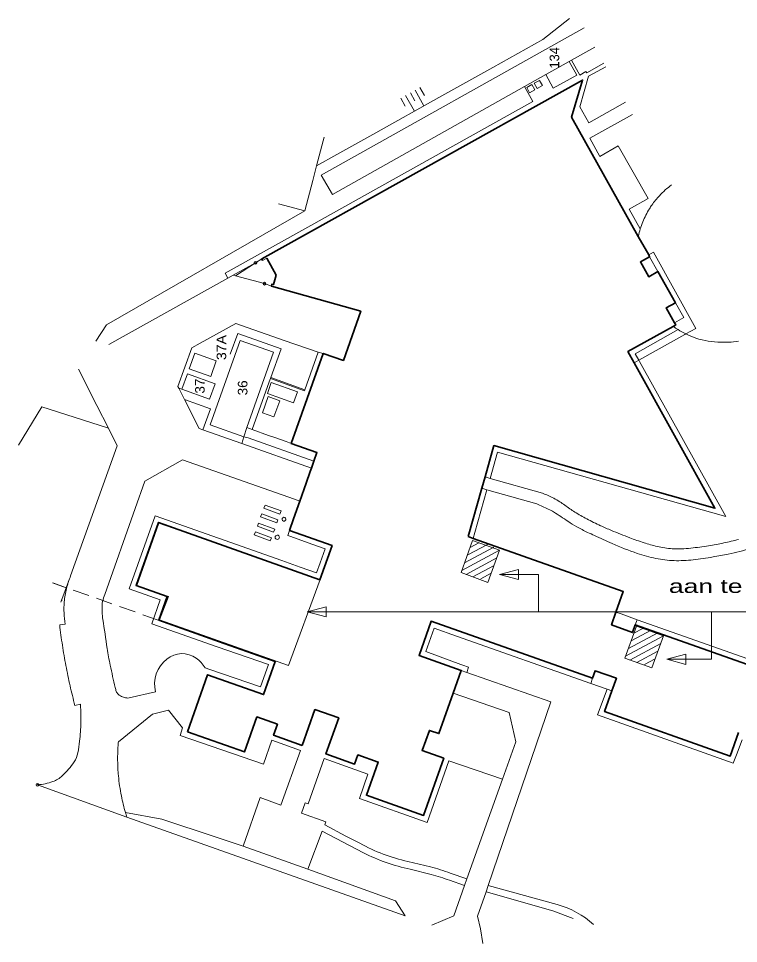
# Model space of a CAD drawing. Extents: x 295824 to 414724, y 24924 to 109024.
# Drawn here: x 390118 to 403291, y 57517 to 74434 of the extents above; entities that cross this region are included whole.
import ezdxf

# ---------------------------------------------------------------- set-up
doc = ezdxf.new("R2010")
doc.units = 0
doc.header["$LTSCALE"] = 100
doc.header["$PDMODE"] = 32
doc.header["$PDSIZE"] = 50
doc.linetypes.add('MEDIUM_DASHED', pattern=[4.5, 3, -1.5])
for name, color, linetype, lineweight in [('16', 7, 'Continuous', 13), ('19', 7, 'Continuous', 13), ('20', 7, 'Continuous', 13), ('22', 7, 'Continuous', 13), ('24', 7, 'Continuous', 13), ('25', 7, 'Continuous', 13), ('26', 7, 'Continuous', 13), ('32', 7, 'Continuous', 13), ('4', 7, 'Continuous', 35), ('40', 7, 'Continuous', 13), ('51', 7, 'Continuous', 13), ('52', 7, 'Continuous', 13), ('58', 7, 'Continuous', 35), ('62', 7, 'Continuous', 13)]:
    doc.layers.add(name, color=color, linetype=linetype, lineweight=lineweight)
doc.layers.add('57', color=7, linetype='Continuous')

msp = doc.modelspace()

# ---------------------------------------------------------------- linework, layer by layer
at = {"layer": '16'}
for p, q in [((398339.7, 64625.4), (398697.8, 64817)), ((398380.9, 64760.9), (398542, 64847.1)), ((398228.2, 64338.8), (398920.2, 64709.2)), ((398279.1, 64479.5), (398814.6, 64766.1)), ((398306.8, 64267.5), (398869.3, 64568.6)), ((398433.3, 64221.8), (398818.4, 64427.9)), ((398575.6, 64184.5), (398767.5, 64287.2)), ((398915.6, 64265.6), (399633.3, 64265.6)), ((399633.3, 63582.1), (399633.3, 64265.6)), ((401379, 63194.2), (401540.1, 63280.5)), ((401226.3, 62772.2), (401918.3, 63142.6)), ((401277.2, 62912.9), (401812.7, 63199.5)), ((401337.8, 63058.7), (401695.9, 63250.4)), ((401305, 62700.9), (401867.4, 63001.9)), ((401431.4, 62655.1), (401816.5, 62861.2)), ((401573.7, 62617.9), (401765.6, 62720.6))]:
    msp.add_line(p, q, dxfattribs=at)
for points in [[(398214.5, 64301), (398707.8, 64122.4), (398920.5, 64710.1), (398427.2, 64888.6)], [(401212.6, 62734.3), (401706, 62555.8), (401918.7, 63143.5), (401425.3, 63322)]]:
    msp.add_lwpolyline(points, close=True, dxfattribs=at)
msp.add_lwpolyline([(401980.4, 62715.6), (402798, 62715.6), (402798, 63582.1)], dxfattribs=at)
at = {"layer": '19'}
for p, q in [((394584.9, 70006.1), (394661.4, 70048.8)), ((395148.2, 67405.7), (394671.7, 67575.8)), ((394896.6, 67444.5), (394686.6, 67519.5)), ((395220.4, 67607.9), (395148.2, 67405.7)), ((394896.6, 67444.5), (394790.8, 67147.9)), ((394790.8, 67147.9), (394580.8, 67222.8)), ((404266.6, 62331.9), (401403.2, 63344.3))]:
    msp.add_line(p, q, dxfattribs=at)
for points in [[(400191.8, 73647.3), (400330.6, 73398.7), (399902.8, 73159.8), (399764.6, 73407.3)], [(399704.8, 73206.6), (399607.9, 73152.5), (399553.8, 73249.4), (399650.7, 73303.5)], [(399470, 73075.5), (399566.9, 73129.6), (399512.8, 73226.5), (399415.9, 73172.4)], [(394239.1, 66785.5), (393623, 67003.2), (394173.5, 68548.3), (394785.8, 68331.4), (394298, 66952)], [(393342, 68312.4), (393737.7, 68171.5), (393637, 67888.9), (393241.4, 68029.8)], [(393613.7, 67474.6), (393713.7, 67755.4), (393207.8, 67935.6), (393107.8, 67654.9)]]:
    msp.add_lwpolyline(points, close=True, dxfattribs=at)
for points in [[(395220.4, 67607.9), (394743.2, 67776.3), (394671.7, 67575.8)], [(400975, 62135.3), (400840.6, 61758.2), (403138.8, 60943.5)]]:
    msp.add_lwpolyline(points, dxfattribs=at)
at = {"layer": '20'}
msp.add_lwpolyline([(393241.4, 68029.8), (393342, 68312.4), (393737.7, 68171.5), (393637, 67888.9)], close=True, dxfattribs=at)
at = {"layer": '22'}
for p, q in [((394455, 69965.8), (394567.6, 70037.9)), ((394617.8, 69585.3), (394744.1, 69540.6)), ((394686.6, 67519.5), (394580.8, 67222.8))]:
    msp.add_line(p, q, dxfattribs=at)
msp.add_lwpolyline([(401380.6, 68138.5), (401465.7, 68185.8), (402310.4, 68655.1), (402329.8, 68665.9), (402511.9, 68767.1), (401737.8, 70160.2), (401647.7, 70110.1)], dxfattribs=at)
at = {"layer": '24'}
msp.add_line((395432.7, 63582.1), (407470.1, 63582.1), dxfattribs=at)
at = {"layer": '25'}
for points in [[(400201.2, 74434.5), (399709.1, 74048.6), (398798.9, 73540.2), (397811.2, 72988.5), (396656.4, 72343.5), (395942.3, 71944.7), (395573.2, 71738.5)], [(395355.3, 70914.2), (391725.5, 68834.5), (391530.3, 68535.7)], [(391762.7, 66939.2), (391288.2, 67092.3), (390547.7, 67331.3), (390118.2, 66628.2)]]:
    msp.add_lwpolyline(points, dxfattribs=at)
at = {"layer": '26'}
for p, q in [((397375.8, 73123.5), (397535.4, 72834.5)), ((397463.3, 73171.8), (397543.5, 73026.7)), ((397113.2, 72978.4), (397193.3, 72833.3)), ((397200.7, 73026.8), (397360.8, 72736.9)), ((397288.2, 73075.1), (397368.4, 72930))]:
    msp.add_line(p, q, dxfattribs=at)
at = {"layer": '32'}
for p in [(394629.7, 65536.4), (394899.8, 65370)]:
    msp.add_line(p, (394921.6, 65429.1), dxfattribs=at)
msp.add_lwpolyline([(394899.8, 65370), (394607.1, 65477.6), (394629.7, 65536.4)], dxfattribs=at)
for points in [[(394571.2, 65377), (394548.3, 65318.2), (394843.1, 65209.7), (394863.3, 65266.2)], [(394805.3, 65095.4), (394785, 65038.9), (394490.1, 65147.4), (394511.8, 65204.2)], [(394451.5, 65046.4), (394429.2, 64988.5), (394723.5, 64878.6), (394745, 64937.4)]]:
    msp.add_lwpolyline(points, close=True, dxfattribs=at)
for centre, radius, start, end in [((394992.2, 65258.5), 58.2, 110.85429, 148.54529), ((394974, 65272.4), 40.5, 38.66887, 93.52701), ((395004.6, 65283.3), 62.3, 174.88401, 210.92845), ((394976.9, 65288.1), 45, 235.11752, 280.94338), ((394971.5, 65278.9), 37.6, 291.80741, 337.95407), ((394967.7, 65280.4), 41.7, 337.95407, 24.52464), ((394852.4, 64946.8), 38.4, 113.54211, 160.33052), ((394852.6, 64946.2), 39, 67.13969, 113.54211), ((394852.6, 64946.3), 39, 24.60068, 67.13969), ((394852.6, 64946.7), 38.6, 160.33052, 203.06541), ((394852.6, 64946.7), 38.6, 203.06541, 245.79546), ((394853, 64946.5), 38.6, 245.06344, 293.39196), ((394853, 64946.5), 38.6, 293.39196, 341.72546), ((394853.2, 64946.5), 38.4, 341.72546, 24.60068)]:
    msp.add_arc(centre, radius, start, end, dxfattribs=at)
at = {"layer": '4', "lineweight": 13}
for p, q in [((391033.8, 64138.9), (390894.9, 63757.1)), ((390742.8, 64114.9), (390991.8, 64024.2))]:
    msp.add_line(p, q, dxfattribs=at)
at = {"layer": '4', "linetype": 'MEDIUM_DASHED', "lineweight": 13}
msp.add_line((392675.1, 63429.9), (390767.5, 64105.4), dxfattribs=at)
at = {"layer": '4'}
for points in [[(398345.9, 64959.9), (398595.1, 65842.4), (398653.8, 66050.3), (398815.4, 66622.8), (402860.5, 65478.5), (401380.6, 68138.5), (401266.8, 68342.9), (402095.4, 68803.3), (402141.6, 68829), (402119.2, 68869.1), (401966.3, 69142.6), (402135.7, 69237.2), (401817.5, 69806.4), (401648.2, 69711.7), (401496.4, 69983.2), (401665.8, 70077.8), (401647.7, 70110.1), (401457.9, 70449.7), (400238.2, 72631.6), (400437.6, 73309.6), (394567.6, 70037.9), (394584.9, 70006.1)], [(394661.4, 70048.8), (394832.4, 69742.4), (394783.3, 69568), (394754.1, 69576.2), (394744.1, 69540.6), (396379.6, 69080.3), (396062.5, 68181.5), (395695.1, 68310.4), (395107.3, 66663.3)], [(393211, 61389.5), (393579, 62431.5), (394602, 62070.1), (394814.8, 62673.8), (393798.6, 63033.9), (392682.8, 63429.3), (392836.5, 63863.2), (392270.3, 64066.1), (392679.8, 65218.8), (395633.8, 64169.4), (395856.4, 64796), (395078.1, 65072.5), (395149, 65281.9), (395265.4, 65609.8), (395382, 65938.4), (395456.7, 66149.5), (395478.9, 66212.2), (395523.6, 66339.1), (395577.3, 66495.6), (395107.3, 66663.3)], [(398345.9, 64959.9), (398438.8, 64927), (401183.2, 63954), (401049.6, 63577.2), (400968.8, 63343.5), (401353.9, 63204.8), (401403.2, 63344.3), (404266.6, 62331.9)], [(403292.1, 61376.1), (403138.8, 60943.5), (400840.6, 61758.2), (400975, 62135.3), (401057.6, 62367.2), (400668.4, 62505.8), (400619.8, 62368.1), (397666.9, 63410.6), (397447.5, 62784.9), (398219.5, 62511.7), (398071.4, 62093), (397810.4, 61355.5), (397636.8, 61414.1), (397502, 61043.9), (397897.9, 60903.7), (397528.5, 59859.5), (396484.4, 60229.1), (396699.9, 60834.8), (396326.9, 60967.6), (396266.9, 60799), (395743.7, 60985.3), (395977.4, 61641.5), (395542.2, 61796.3), (395308.8, 61139.6)], [(395308.8, 61139.6), (394784.7, 61325.9), (394856.5, 61528.5), (394479.5, 61661.9), (394252.7, 61021), (393211, 61389.5)]]:
    msp.add_lwpolyline(points, dxfattribs=at)
at = {"layer": '40'}
for p, q in [((395355.3, 70914.2), (394876.8, 71043.2)), ((394455, 69965.8), (394045.2, 69741.2)), ((394086.2, 69730), (394455, 69965.8)), ((394086.2, 69730), (394617.8, 69585.3)), ((394728.6, 67848.5), (394735.4, 67867.3)), ((395356.9, 67645.6), (394735.4, 67867.3))]:
    msp.add_line(p, q, dxfattribs=at)
for points in [[(395355.3, 70914.2), (395502.3, 71470.2), (395573.2, 71738.5), (395693.7, 72194.5), (395711.9, 72263.5)], [(394045.2, 69741.2), (394086.2, 69730), (394617.8, 69585.3)], [(395356.9, 67645.6), (395350.2, 67626.7), (394728.6, 67848.5)]]:
    msp.add_lwpolyline(points, dxfattribs=at)
for p in [(394455, 69965.8), (394617.8, 69585.3)]:
    msp.add_point(p, dxfattribs=at)
at = {"layer": '51'}
for p, q in [((400548.3, 73377.1), (400863.6, 73553.1)), ((400390.3, 72820), (400548.3, 73377.1)), ((399526.9, 72916.1), (399374.9, 73188.4)), ((400552.6, 72527.5), (400390.3, 72820)), ((401226.5, 72901.3), (400552.6, 72527.5)), ((401637.4, 71142.4), (401290.7, 70948.6)), ((401493.4, 70586), (401290.7, 70948.6)), ((401665.8, 70077.8), (401817.5, 69806.4)), ((402184.7, 68744.6), (401399.6, 68304.3)), ((394925.3, 68394.2), (394735.4, 67867.3)), ((395601, 68329.2), (395356.9, 67645.6)), ((393107.8, 67654.9), (393049, 67672.9)), ((394203.2, 66659), (395478.9, 66212.2)), ((394317.8, 66767.1), (394239.1, 66785.5)), ((394317.8, 66767.1), (395523.6, 66339.1)), ((391072.5, 64241.9), (391925.8, 66616.4)), ((398747.4, 66023.8), (398882, 66505.7)), ((398882, 66505.7), (403059.5, 65327.6)), ((392428.3, 65974.8), (393117.2, 66362.1)), ((392143.7, 64001.5), (392619.6, 65338.9)), ((395044, 64978.6), (395078.1, 65072.5)), ((390971.8, 63357.9), (390871.9, 63345.9)), ((397572.7, 62856.4), (397722.3, 63282.5)), ((397722.3, 63282.5), (398132.5, 63138.1)), ((401439.3, 63439), (404392.5, 62396.9)), ((400589.7, 62272.7), (398132.5, 63138.1)), ((394547.4, 62209.9), (394690, 62619.8)), ((392627.5, 62118), (392141.4, 62008)), ((400885.9, 62167.1), (400711.9, 61699.2)), ((398714.1, 58579.2), (399856.7, 61938.2)), ((391150.8, 61868.3), (391250.1, 61891.9)), ((403356.9, 61244.5), (403252, 60966.7)), ((396356.7, 60168.9), (396507.4, 60611.1)), ((390467.6, 60420.9), (392101.7, 59830.4)), ((395297.1, 59903.4), (395739.7, 59744.3)), ((392101.7, 59830.4), (397190.5, 58020.7)), ((395413.4, 58877.7), (395675.3, 59574.3)), ((395675.3, 59574.3), (396427.5, 59176.2)), ((397653.9, 58916.4), (397241.2, 59018.2)), ((397283.7, 58874.9), (397669.3, 58778.8)), ((398714.1, 58579.2), (399971.9, 58228.1)), ((397012.8, 58296.1), (397190.5, 58020.7)), ((399895.9, 58113.1), (400267, 57974.7))]:
    msp.add_line(p, q, dxfattribs=at)
for points in [[(400468.6, 74262.4), (395657.3, 71566.3), (395860.2, 71214.2)], [(400663.5, 73912.2), (400235.4, 73671.8), (400191.8, 73647.3), (399764.6, 73407.3), (399374.9, 73188.4), (396548.6, 71600.9), (395860.2, 71214.2)], [(400828.5, 73616), (400513.6, 73440.2), (400500.4, 73463.7), (400386.9, 73400.4), (400235.4, 73671.8)], [(399526.9, 72916.1), (396505.5, 71229.4), (395469.7, 70651.2), (393899.9, 69774.8), (393949.8, 69687.8)], [(401637.4, 71142.4), (401092.5, 72106.4), (400751.4, 71912.6), (400568.2, 72245.5), (401349.4, 72680.7)], [(394045.2, 69741.2), (393949.8, 69687.8), (391770.3, 68469.4)], [(402119.2, 68869.1), (402288.9, 68963.2), (402135.7, 69237.2)], [(393049, 67672.9), (393035.9, 67701.4), (393292.2, 68411.5), (393440.8, 68494.4), (394095, 68859.3), (394980.4, 68547.6), (395601, 68329.2), (395695.1, 68310.4)], [(394925.3, 68394.2), (394128.5, 68671.7), (393993.8, 68296)], [(403059.5, 65327.6), (401480, 68160.2), (401465.7, 68185.8), (401399.6, 68304.3)], [(391925.8, 66616.4), (391762.7, 66939.2), (391551.2, 67357.6), (391214.7, 68023.6)], [(394728.6, 67848.5), (394707.2, 67789), (394393.2, 66918.1)], [(393155.1, 67464.3), (393629.4, 67293.5), (393493.3, 66910.7), (393424.1, 66935.6), (393155.1, 67464.3), (393049, 67672.9)], [(393493.3, 66910.7), (394203.2, 66659), (394239.1, 66785.5)], [(394298, 66952), (394393.2, 66918.1), (394694.1, 66810.5), (394788.4, 66777.1)], [(394788.4, 66777.1), (395017.6, 66695.3), (395107.3, 66663.3)], [(393117.2, 66362.1), (395166.9, 65644.3), (395265.4, 65609.8)], [(398653.8, 66050.3), (398747.4, 66023.8), (399703.7, 65753.1)], [(392428.3, 65974.8), (392251.3, 65472), (391696.8, 63897.1)], [(398687.6, 65815.9), (398468.8, 65034.1), (398438.8, 64927)], [(399599.1, 65555.4), (398687.6, 65815.9), (398595.1, 65842.4)], [(395573, 64296.9), (395272.7, 64402.9), (394938.2, 64520.9), (392619.6, 65338.9)], [(395044, 64978.6), (395101.7, 64958), (395482.7, 64822.6), (395728.7, 64735.2)], [(395728.7, 64735.2), (395636.7, 64476.3), (395573, 64296.9)], [(392143.7, 64001.5), (392711.3, 63802.4), (392558, 63361.5)], [(401403.2, 63344.3), (401439.3, 63439), (401143.9, 63545), (401049.6, 63577.2)], [(394690, 62619.8), (393755.5, 62944.9), (392558, 63361.5)], [(397572.7, 62856.4), (398212.6, 62619.5), (398249.7, 62605.7)], [(399856.7, 61938.2), (398320.5, 62472.4), (398349.8, 62568.6), (398249.7, 62605.7), (398212.6, 62619.5)], [(393530.5, 62559.8), (393617.2, 62530), (394547.4, 62209.9)], [(400619.8, 62368.1), (400589.7, 62272.7), (400885.9, 62167.1), (400975, 62135.3)], [(391946, 61206.2), (392568.6, 61712.7), (392862.6, 61783.4), (393121.8, 61460.2), (393075.4, 61321.9)], [(403252, 60966.7), (403195.2, 60816.4), (400711.9, 61699.2)], [(393714.6, 59469.5), (394227.6, 59295.7), (394537.9, 60189), (394918.5, 60048.1), (395277.5, 61049.6), (394755.3, 61233), (394598, 60799.2), (393075.4, 61321.9)], [(396507.4, 60611.1), (395713.1, 60897.9), (395417.8, 60071), (395363.9, 60092.2), (395297.1, 59903.4)], [(396356.7, 60168.9), (397593.8, 59727.2), (397989.8, 60856.9), (398970.7, 60523.7), (398321.9, 58698.5), (398018.1, 58803)], [(393714.6, 59469.5), (392738.5, 59789), (392075.9, 59913.1)], [(396365.3, 59350.5), (396107.6, 59482.3), (395725.1, 59688.6), (395739.7, 59744.3)], [(394227.6, 59295.7), (395413.4, 58877.7), (397012.8, 58296.1)], [(398004.3, 58672.4), (398279.5, 58577), (398083.2, 58022.9), (397677.6, 57854.4)], [(399895.9, 58113.1), (398675.9, 58461.7), (398515, 58018.5), (398573.7, 57784.8), (398612.4, 57517.1)]]:
    msp.add_lwpolyline(points, dxfattribs=at)
for centre, radius, start, end in [((403001.2, 70120), 1578.2, 126.29056, 137.1502), ((402996.6, 70113.7), 1579, 136.86919, 144.86761), ((403004.2, 70125.8), 1577.5, 148.248, 158.08467), ((403014.1, 70141.1), 1578, 146.04811, 148.90934), ((403001.2, 70120), 1578.2, 162.82504, 167.93957), ((402996.2, 70106.1), 1577.5, 157.31277, 162.2913), ((403017.9, 70107.6), 1597.5, 234.73007, 238.56524), ((403017.9, 70107.6), 1597.5, 238.56524, 244.48705), ((403061.5, 70092.3), 1603.2, 242.84296, 249.97212), ((402989.1, 70111.9), 1598.5, 252.65339, 269.25839), ((403030.9, 70108.4), 1596.1, 272.9189, 279.38393), ((403030.9, 70108.4), 1596.1, 267.75368, 272.9189), ((398555.4, 62916.4), 3060.2, 63.73678, 67.96053), ((399468.8, 64767.6), 996, 56.32959, 63.73678), ((397881.9, 61370.7), 4523.4, 64.74941, 67.69024), ((397123.8, 61247.5), 5225.7, 53.87718, 56.32959), ((399371.3, 64528.6), 1031.8, 58.58977, 64.74941), ((396669.8, 60104.5), 6215.6, 55.7123, 58.58977), ((400967.1, 66513.5), 1293.7, 233.87718, 238.80723), ((402475.3, 69004.6), 4205.8, 238.80723, 242.2048), ((401462.5, 67133.6), 2291.9, 235.7123, 240.45176), ((401915.7, 67933), 3210.9, 240.45176, 244.44182), ((403071.4, 70135.6), 5484.2, 242.2048, 245.18002), ((402969.1, 69914.3), 5240.4, 245.18002, 247.51654), ((407255.7, 79099.5), 15588.6, 244.44183, 244.94759), ((407255.7, 79099.5), 15588.6, 244.94759, 246.25241), ((406699.2, 78926.9), 14994.5, 247.51654, 248.89777), ((403234.5, 69959.6), 5603.1, 246.25241, 251.30735), ((402940.9, 69188.2), 4555.8, 248.89777, 252.38967), ((402690.8, 68400.3), 3729.1, 252.38968, 256.2494), ((402005.3, 69479.7), 4747.3, 278.95687, 282.34377), ((401652.9, 71090), 6395.7, 282.34377, 284.86156), ((402352.7, 67353.3), 2851.8, 251.30735, 258.39517), ((402153, 66202.5), 1466.4, 256.2494, 267.13568), ((402188.5, 66912.1), 2176.9, 267.13568, 276.06602), ((401730, 71226.6), 6515.7, 276.06602, 278.95687), ((401914.2, 70161), 5648.3, 279.28211, 282.17072), ((401537.4, 71907.7), 7435.1, 282.17071, 285.46087), ((402188.6, 66554), 2035.8, 258.39517, 267.88214), ((402194, 66701.4), 2183.2, 267.88214, 277.04242), ((401309.9, 73858.3), 9394.5, 277.04242, 279.28211), ((392569.1, 63625.1), 1618.7, 157.59913, 166.33894), ((392575.8, 63622.9), 1625.8, 166.31962, 175.05942), ((391921.4, 63711.8), 271.9, 165.51022, 179.4869), ((392574.4, 63543.1), 946.3, 158.03226, 165.51022), ((392577.4, 63622.8), 1627.4, 175.06279, 182.21363), ((396127.4, 63674.2), 4478, 179.4869, 181.36323), ((392578.2, 63623.1), 1628.2, 182.22234, 189.37318), ((392523.1, 63588.4), 872.7, 181.36323, 185.61426), ((392880.3, 63623.5), 1231.6, 185.61426, 188.32056), ((496662.1, 78801.7), 106117.5, 188.32056, 188.61209), ((401124.1, 64518.9), 10319.1, 186.52713, 188.62019), ((401168.9, 64524.8), 10364.4, 188.61557, 190.70863), ((397154.3, 63731.1), 5474.9, 188.61209, 191.8452), ((393110.3, 62383.4), 435.4, 53.34093, 129.55669), ((401169.4, 64524.9), 10364.9, 190.70868, 192.77844), ((405518.1, 65485.3), 14020.7, 191.8452, 193.56084), ((393175, 62266.5), 567.3, 127.0737, 195.1798), ((393098.9, 62320.8), 493.3, 28.9771, 56.61769), ((401183.6, 64528.4), 10379.4, 192.77998, 194.84974), ((405518.1, 65485.3), 14020.7, 193.56084, 193.86537), ((392108.2, 62241.9), 233.4, 209.96911, 223.92548), ((392108.2, 62241.9), 233.4, 223.92548, 237.88186), ((392108.2, 62241.9), 233.4, 237.88186, 256.92832), ((392118, 62267.7), 260.8, 256.10746, 275.15393), ((387126.6, 61571.5), 4135.9, 1.68739, 4.44382), ((389375.9, 61637.2), 1885.7, 357.60767, 1.70362), ((385248.3, 61811), 6016.9, 354.34626, 357.59535), ((388875.3, 61451.1), 2372.1, 349.17636, 354.36574), ((395379.4, 60898.2), 3447.3, 175.30239, 180.57924), ((395379.4, 60898.2), 3447.3, 174.87442, 175.30239), ((390764.7, 61089.2), 448.3, 325.95767, 349.25694), ((389866.7, 61698.1), 1533.4, 313.37054, 325.89), ((395379.4, 60898.2), 3447.3, 180.57924, 185.24038), ((390596.3, 60924.5), 470, 288.46567, 313.47185), ((395379.4, 60898.2), 3447.3, 185.24038, 191.42851), ((390424.3, 61323.3), 903.4, 272.74207, 290.80053), ((395379.4, 60898.2), 3447.3, 191.42851, 196.60432), ((395379.4, 60898.2), 3447.3, 196.60433, 198.04367), ((397942, 62185.2), 3243.7, 240.91681, 257.52249), ((398052.7, 62427.3), 3634.7, 243.43983, 257.7842), ((397111.4, 56534.3), 2443.2, 68.21629, 77.1705), ((396700.3, 55145.8), 3760, 69.70629, 75.06476), ((399580.1, 56720.2), 1558, 47.15378, 75.43561)]:
    msp.add_arc(centre, radius, start, end, dxfattribs=at)
msp.add_point((390467.6, 60420.9), dxfattribs=at)
at = {"layer": '52'}
for p, q in [((398320.5, 62472.4), (398219.5, 62511.7)), ((398321.9, 58698.5), (398279.5, 58577)), ((398714.1, 58579.2), (398675.9, 58461.7))]:
    msp.add_line(p, q, dxfattribs=at)
msp.add_lwpolyline([(398071.4, 62093), (399092.7, 61740.2), (399214.5, 61207.5), (398970.7, 60523.7)], dxfattribs=at)
at = {"layer": '58'}
msp.add_line((390903.3, 63796.6), (390916.9, 63803), dxfattribs=at)
at = {"layer": '62'}
for points in [[(392281.5, 64066.3), (392684.5, 65203.2), (395639, 64171.7), (395059.7, 62603.8), (392696.3, 63433.8), (392860.9, 63862)], [(398915.6, 64265.6), (399264.6, 64359.1), (399264.6, 64172.1)], [(395401.2, 63582.3), (395750.1, 63675.8), (395750.1, 63488.8)], [(401980.4, 62715.6), (402329.4, 62809.1), (402329.4, 62622.1)]]:
    msp.add_lwpolyline(points, close=True, dxfattribs=at)

# ---------------------------------------------------------------- texts
at = {"layer": '24', "width": 1.45}
msp.add_text('aan te passen gedeelten', height=250, dxfattribs=at).set_placement((402017.3, 63928.4))
at = {"layer": '57'}
msp.add_text('134', height=175, rotation=90, dxfattribs=at).set_placement((400010.7, 73520))
for s, width, p in [('37A', 1.1, (393918, 68187.6)), ('37', 1.05, (393524.3, 67574.2)), ('36', 1.05, (394306.6, 67542.4))]:
    msp.add_text(s, height=175, rotation=90, dxfattribs=dict(at, width=width)).set_placement(p)

doc.saveas('drawing.dxf')
